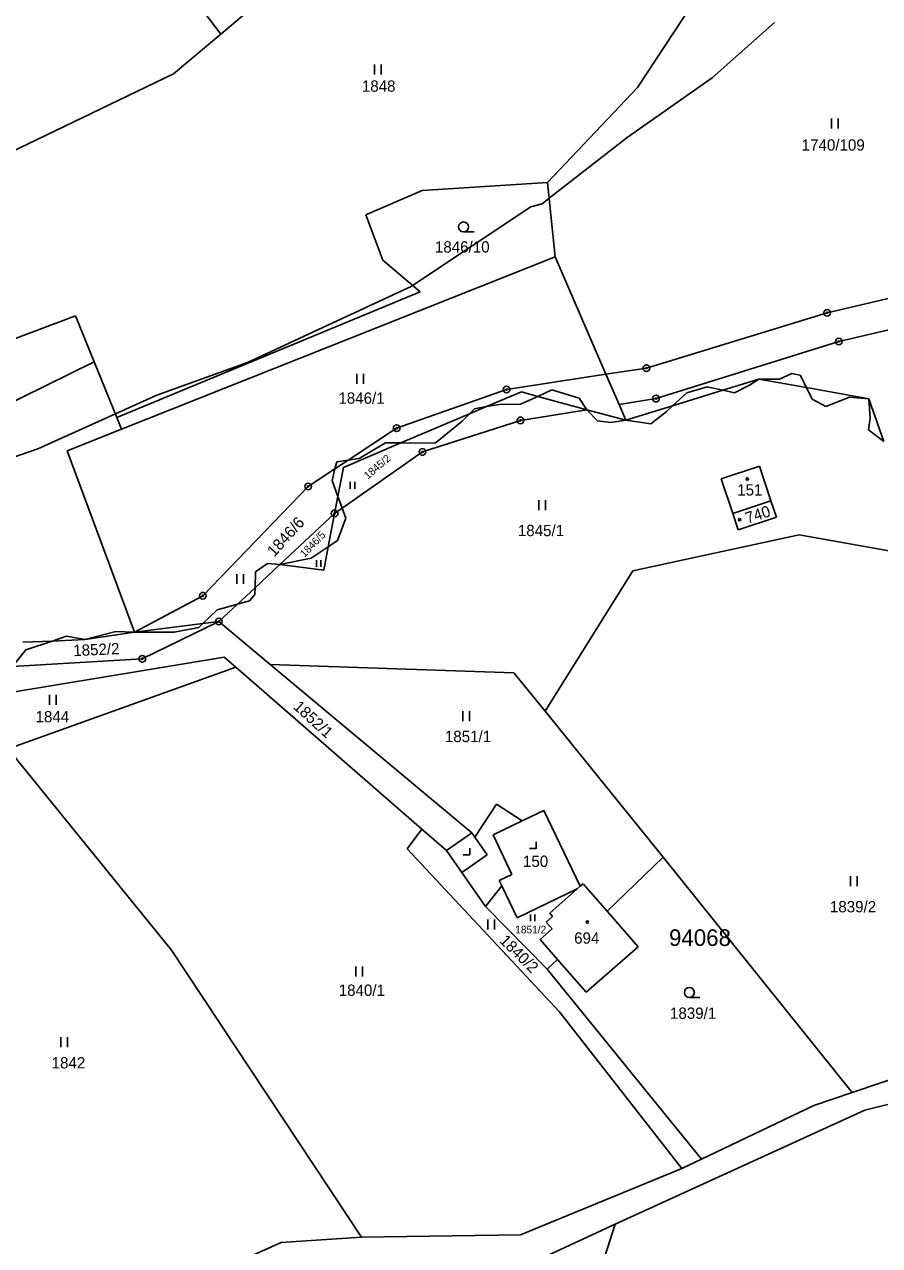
# Model space of a CAD drawing. Extents: x -445050 to -440454, y -1134563 to -1129741.
# Drawn here: x -443566 to -443437.5, y -1133613.8 to -1133430.3 of the extents above; entities that cross this region are included whole.
import ezdxf

# ---------------------------------------------------------------- set-up
doc = ezdxf.new("R2010")
doc.units = 0
for name, color, linetype in [('Vrstva 1', 7, 'Continuous'), ('Vrstva 16', 7, 'Continuous'), ('Vrstva 18', 7, 'Continuous'), ('Vrstva 19', 7, 'Continuous'), ('Vrstva 24', 7, 'Continuous'), ('Vrstva 25', 7, 'Continuous'), ('Vrstva 3', 7, 'Continuous'), ('Vrstva 37', 7, 'Continuous'), ('Vrstva 4', 7, 'Continuous'), ('Vrstva 52', 7, 'Continuous'), ('Vrstva 53', 7, 'Continuous'), ('Vrstva 6', 7, 'Continuous')]:
    doc.layers.add(name, color=color, linetype=linetype)

msp = doc.modelspace()

# ---------------------------------------------------------------- linework, layer by layer
at = {"layer": 'Vrstva 1'}
for p, q in [((-443551.44, -1133491.11), (-443486.28, -1133465.21)), ((-443599.13, -1133502.43), (-443555.56, -1133480.99)), ((-443551.44, -1133491.11), (-443552.14, -1133489.36)), ((-443559.63, -1133494.37), (-443551.44, -1133491.11)), ((-443453.87, -1133501.88), (-443453.05, -1133504.34)), ((-443458.81, -1133506.24), (-443459.62, -1133503.79)), ((-443453.05, -1133504.34), (-443458.81, -1133506.24)), ((-443482.53, -1133559.8), (-443487.99, -1133548.43)), ((-443470.05, -1133555.41), (-443478.47, -1133563.55)), ((-443482.99, -1133560.2), (-443482.53, -1133559.8)), ((-443482.53, -1133559.8), (-443482.09, -1133559.41)), ((-443482.09, -1133559.41), (-443478.47, -1133563.55)), ((-443482.99, -1133560.2), (-443492.02, -1133564.54)), ((-443487.1, -1133563.84), (-443482.99, -1133560.2)), ((-443478.47, -1133563.55), (-443473.82, -1133568.88)), ((-443487.64, -1133565.19), (-443486.67, -1133564.33)), ((-443486.74, -1133566.21), (-443487.64, -1133565.19)), ((-443486.67, -1133564.33), (-443487.1, -1133563.84)), ((-443488.57, -1133567.82), (-443486.74, -1133566.21)), ((-443485.96, -1133570.79), (-443488.57, -1133567.82)), ((-443473.82, -1133568.88), (-443481.62, -1133575.73)), ((-443485.96, -1133570.79), (-443487.47, -1133572.25)), ((-443481.62, -1133575.73), (-443485.96, -1133570.79))]:
    msp.add_line(p, q, dxfattribs=at)
for points in [[(-443506.28, -1133455.25), (-443514.75, -1133458.87)], [(-443506.28, -1133455.25), (-443487.43, -1133454.01)], [(-443486.28, -1133465.21), (-443487.43, -1133454.01)], [(-443512.2, -1133465.69), (-443514.75, -1133458.87)], [(-443445.42, -1133473.61), (-443396.96, -1133462.27)], [(-443512.2, -1133465.69), (-443506.58, -1133470.48)], [(-443478.66, -1133482.85), (-443486.28, -1133465.21)], [(-443393.63, -1133466.27), (-443443.68, -1133477.93)], [(-443506.58, -1133470.48), (-443552.14, -1133489.36)], [(-443472.59, -1133481.92), (-443445.42, -1133473.61)], [(-443579.17, -1133481.9), (-443558.39, -1133474.08)], [(-443558.39, -1133474.08), (-443555.56, -1133480.99)], [(-443443.68, -1133477.93), (-443471.14, -1133486.51)], [(-443555.56, -1133480.99), (-443552.14, -1133489.36)], [(-443493.59, -1133485.15), (-443478.66, -1133482.85)], [(-443478.66, -1133482.85), (-443472.59, -1133481.92)], [(-443476.69, -1133487.4), (-443478.66, -1133482.85)], [(-443461.09, -1133485.25), (-443455.7, -1133483.58)], [(-443455.7, -1133483.58), (-443448.55, -1133484.85)], [(-443510.11, -1133490.96), (-443493.59, -1133485.15)], [(-443496.62, -1133487.72), (-443491.36, -1133485.49)], [(-443491.36, -1133485.49), (-443488.89, -1133486.17)], [(-443488.89, -1133486.17), (-443481.52, -1133488.18)], [(-443471.14, -1133486.51), (-443476.69, -1133487.4)], [(-443468.64, -1133487.59), (-443461.09, -1133485.25)], [(-443448.55, -1133484.85), (-443439.14, -1133486.52)], [(-443439.14, -1133486.52), (-443436.92, -1133492.94)], [(-443499.18, -1133488.81), (-443496.62, -1133487.72)], [(-443481.52, -1133488.18), (-443491.51, -1133489.78)], [(-443481.52, -1133488.18), (-443475.67, -1133489.77)], [(-443476.69, -1133487.4), (-443475.67, -1133489.77)], [(-443475.67, -1133489.77), (-443468.64, -1133487.59)], [(-443509.48, -1133493.18), (-443499.18, -1133488.81)], [(-443491.51, -1133489.78), (-443506.22, -1133494.53)], [(-443517.4, -1133495.75), (-443510.11, -1133490.96)], [(-443518.11, -1133496.84), (-443509.48, -1133493.18)], [(-443559.63, -1133494.37), (-443549.51, -1133521.63)], [(-443519.38, -1133497.05), (-443517.4, -1133495.75)], [(-443506.22, -1133494.53), (-443518.3, -1133502.97)], [(-443523.42, -1133499.71), (-443519.38, -1133497.05)], [(-443518.11, -1133496.84), (-443518.94, -1133501.21)], [(-443461.33, -1133498.56), (-443455.59, -1133496.66)], [(-443455.59, -1133496.66), (-443453.87, -1133501.88)], [(-443459.62, -1133503.79), (-443461.33, -1133498.56)], [(-443539.23, -1133516.13), (-443523.42, -1133499.71)], [(-443518.94, -1133501.21), (-443519.43, -1133503.76)], [(-443518.3, -1133502.97), (-443519.43, -1133503.76)], [(-443453.87, -1133501.88), (-443459.62, -1133503.79)], [(-443519.43, -1133503.76), (-443527.66, -1133511.46)], [(-443519.43, -1133503.76), (-443520.39, -1133508.77)], [(-443449.65, -1133506.99), (-443474.61, -1133512.38)], [(-443421.76, -1133511.95), (-443449.65, -1133506.99)], [(-443520.39, -1133508.77), (-443521.06, -1133512.3)], [(-443527.66, -1133511.46), (-443531.38, -1133514.94)], [(-443527.66, -1133511.46), (-443521.06, -1133512.3)], [(-443474.61, -1133512.38), (-443487.82, -1133533.5)], [(-443531.38, -1133514.94), (-443534.02, -1133517.4)], [(-443549.51, -1133521.63), (-443539.23, -1133516.13)], [(-443534.02, -1133517.4), (-443536.82, -1133520.02)], [(-443549.51, -1133521.63), (-443539.23, -1133520.33)], [(-443536.82, -1133520.02), (-443548.33, -1133525.61)], [(-443539.23, -1133520.33), (-443536.82, -1133520.02)], [(-443536.82, -1133520.02), (-443529.11, -1133526.46)], [(-443566.28, -1133523.13), (-443561.9, -1133522.94)], [(-443561.9, -1133522.94), (-443556.95, -1133522.73)], [(-443556.95, -1133522.73), (-443549.51, -1133521.63)], [(-443573.35, -1133531.52), (-443536.03, -1133525.36)], [(-443568.51, -1133539.16), (-443534.27, -1133526.89)], [(-443548.33, -1133525.61), (-443567.83, -1133526.76)], [(-443534.27, -1133526.89), (-443536.03, -1133525.36)], [(-443506.32, -1133551.22), (-443534.27, -1133526.89)], [(-443529.11, -1133526.46), (-443492.49, -1133527.73)], [(-443498.8, -1133551.77), (-443529.11, -1133526.46)], [(-443492.49, -1133527.73), (-443487.82, -1133533.5)], [(-443487.82, -1133533.5), (-443470.05, -1133555.41)], [(-443568.51, -1133539.16), (-443543.96, -1133569.4)], [(-443498.34, -1133552.43), (-443495.12, -1133547.46)], [(-443495.12, -1133547.46), (-443491.23, -1133549.98)], [(-443487.99, -1133548.43), (-443491.23, -1133549.98)], [(-443506.32, -1133551.22), (-443508.51, -1133554.18)], [(-443502.62, -1133554.44), (-443506.32, -1133551.22)], [(-443498.8, -1133551.77), (-443502.62, -1133554.44)], [(-443498.34, -1133552.43), (-443498.8, -1133551.77)], [(-443508.51, -1133554.18), (-443485.69, -1133578.6)], [(-443502.62, -1133554.44), (-443500.31, -1133557.75)], [(-443470.05, -1133555.41), (-443441.64, -1133590.79)], [(-443500.31, -1133557.75), (-443496.75, -1133562.85)], [(-443496.75, -1133562.85), (-443494.31, -1133559.75)], [(-443492.02, -1133564.54), (-443494.31, -1133559.75)], [(-443496.75, -1133562.85), (-443487.47, -1133572.25)], [(-443543.96, -1133569.4), (-443515.38, -1133612.54)], [(-443487.47, -1133572.25), (-443464.28, -1133600.79)], [(-443485.69, -1133578.6), (-443467.26, -1133602.21)], [(-443441.64, -1133590.79), (-443424.87, -1133585.13)], [(-443447.41, -1133592.74), (-443441.64, -1133590.79)], [(-443439.76, -1133593.44), (-443427.25, -1133590.33)], [(-443464.28, -1133600.79), (-443447.41, -1133592.74)], [(-443477.3, -1133610.57), (-443439.76, -1133593.44)], [(-443467.26, -1133602.21), (-443464.28, -1133600.79)], [(-443491.51, -1133612.18), (-443467.26, -1133602.21)], [(-443477.3, -1133610.57), (-443509.39, -1133710.88)], [(-443488.94, -1133616), (-443477.3, -1133610.57)], [(-443527.48, -1133613.35), (-443515.38, -1133612.54)], [(-443515.38, -1133612.54), (-443491.51, -1133612.18)], [(-443559.66, -1133627.77), (-443527.48, -1133613.35)]]:
    msp.add_lwpolyline(points, dxfattribs=at)
at = {"layer": 'Vrstva 24'}
for centre, radius in [((-443445.42, -1133473.61), 0.5), ((-443445.42, -1133473.61), 0.1), ((-443443.68, -1133477.93), 0.5), ((-443443.68, -1133477.93), 0.1), ((-443472.59, -1133481.92), 0.5), ((-443472.59, -1133481.92), 0.1), ((-443493.59, -1133485.15), 0.5), ((-443493.59, -1133485.15), 0.1), ((-443471.14, -1133486.51), 0.5), ((-443471.14, -1133486.51), 0.1), ((-443491.51, -1133489.78), 0.5), ((-443491.51, -1133489.78), 0.1), ((-443510.11, -1133490.96), 0.5), ((-443510.11, -1133490.96), 0.1), ((-443506.22, -1133494.53), 0.5), ((-443506.22, -1133494.53), 0.1), ((-443523.42, -1133499.71), 0.5), ((-443523.42, -1133499.71), 0.1), ((-443519.43, -1133503.76), 0.5), ((-443519.43, -1133503.76), 0.1), ((-443539.23, -1133516.13), 0.5), ((-443539.23, -1133516.13), 0.1), ((-443536.82, -1133520.02), 0.5), ((-443536.82, -1133520.02), 0.1), ((-443548.33, -1133525.61), 0.5), ((-443548.33, -1133525.61), 0.1)]:
    msp.add_circle(centre, radius, dxfattribs=at)
at = {"layer": 'Vrstva 25'}
for p, q in [((-443513.42, -1133437.78), (-443513.42, -1133436.28)), ((-443512.42, -1133437.78), (-443512.42, -1133436.28)), ((-443444.77, -1133445.91), (-443444.77, -1133444.41)), ((-443443.77, -1133445.91), (-443443.77, -1133444.41)), ((-443500.06, -1133461.46), (-443498.46, -1133461.46)), ((-443516.11, -1133484.3), (-443516.11, -1133482.8)), ((-443515.11, -1133484.3), (-443515.11, -1133482.8)), ((-443517.09, -1133500.05), (-443517.09, -1133499.04)), ((-443516.42, -1133500.05), (-443516.42, -1133499.04)), ((-443488.74, -1133503.29), (-443488.74, -1133501.79)), ((-443487.74, -1133503.29), (-443487.74, -1133501.79)), ((-443522.16, -1133511.78), (-443522.16, -1133510.78)), ((-443521.48, -1133511.78), (-443521.48, -1133510.78)), ((-443534.15, -1133514.37), (-443534.15, -1133512.87)), ((-443533.15, -1133514.37), (-443533.15, -1133512.87)), ((-443562.27, -1133532.52), (-443562.27, -1133531.02)), ((-443561.27, -1133532.52), (-443561.27, -1133531.02)), ((-443500.15, -1133534.97), (-443500.15, -1133533.47)), ((-443499.15, -1133534.97), (-443499.15, -1133533.47)), ((-443441.92, -1133559.8), (-443441.92, -1133558.3)), ((-443440.92, -1133559.8), (-443440.92, -1133558.3)), ((-443496.39, -1133566.31), (-443496.39, -1133564.81)), ((-443495.39, -1133566.31), (-443495.39, -1133564.81)), ((-443490.02, -1133565.02), (-443490.02, -1133564.02)), ((-443489.35, -1133565.02), (-443489.35, -1133564.02)), ((-443516.23, -1133573.35), (-443516.23, -1133571.85)), ((-443515.23, -1133573.35), (-443515.23, -1133571.85)), ((-443466.13, -1133576.51), (-443464.53, -1133576.51)), ((-443560.59, -1133583.99), (-443560.59, -1133582.49)), ((-443559.59, -1133583.99), (-443559.59, -1133582.49))]:
    msp.add_line(p, q, dxfattribs=at)
for points in [[(-443500.13, -1133555.06), (-443499.13, -1133555.06), (-443499.13, -1133554.06)], [(-443490.14, -1133554.11), (-443489.14, -1133554.11), (-443489.14, -1133553.11)]]:
    msp.add_lwpolyline(points, dxfattribs=at)
for centre, radius in [((-443500.06, -1133460.71), 0.75), ((-443457.43, -1133498.57), 0.175), ((-443458.57, -1133504.69), 0.175), ((-443481.44, -1133565.19), 0.175), ((-443466.13, -1133575.76), 0.75)]:
    msp.add_circle(centre, radius, dxfattribs=at)
at = {"layer": 'Vrstva 3'}
for points in [[(-443461.33, -1133498.56), (-443455.59, -1133496.66)], [(-443455.59, -1133496.66), (-443453.87, -1133501.88)], [(-443459.62, -1133503.79), (-443461.33, -1133498.56)], [(-443453.87, -1133501.88), (-443453.05, -1133504.34)], [(-443458.81, -1133506.24), (-443459.62, -1133503.79)], [(-443453.05, -1133504.34), (-443458.81, -1133506.24)], [(-443482.99, -1133560.2), (-443482.53, -1133559.8)], [(-443482.53, -1133559.8), (-443482.09, -1133559.41)], [(-443482.09, -1133559.41), (-443478.47, -1133563.55)], [(-443487.1, -1133563.84), (-443482.99, -1133560.2)], [(-443478.47, -1133563.55), (-443473.82, -1133568.88)], [(-443487.64, -1133565.19), (-443486.67, -1133564.33)], [(-443486.74, -1133566.21), (-443487.64, -1133565.19)], [(-443486.67, -1133564.33), (-443487.1, -1133563.84)], [(-443488.57, -1133567.82), (-443486.74, -1133566.21)], [(-443485.96, -1133570.79), (-443488.57, -1133567.82)], [(-443473.82, -1133568.88), (-443481.62, -1133575.73)], [(-443481.62, -1133575.73), (-443485.96, -1133570.79)]]:
    msp.add_lwpolyline(points, dxfattribs=at)
at = {"layer": 'Vrstva 37'}
for centre in [(-443457.43, -1133498.57), (-443481.44, -1133565.19)]:
    msp.add_circle(centre, 0.175, dxfattribs=at)
at = {"layer": 'Vrstva 4'}
for points in [[(-443452.56, -1133483.57), (-443450.73, -1133482.74)], [(-443450.73, -1133482.74), (-443449.5, -1133482.98)], [(-443466.52, -1133485.63), (-443463.45, -1133484.74)], [(-443463.45, -1133484.74), (-443461.09, -1133485.25)], [(-443459.33, -1133485.63), (-443457.09, -1133484.51)], [(-443457.09, -1133484.51), (-443455.7, -1133483.58)], [(-443455.7, -1133483.58), (-443452.56, -1133483.57)], [(-443449.5, -1133482.98), (-443448.55, -1133484.85)], [(-443491.48, -1133487.34), (-443488.89, -1133486.17)], [(-443488.89, -1133486.17), (-443486.77, -1133485.21)], [(-443486.77, -1133485.21), (-443482.7, -1133486.45)], [(-443482.7, -1133486.45), (-443481.52, -1133488.18)], [(-443468.64, -1133487.59), (-443466.52, -1133485.63)], [(-443461.09, -1133485.25), (-443459.33, -1133485.63)], [(-443448.55, -1133484.85), (-443447.67, -1133486.57)], [(-443447.67, -1133486.57), (-443445.61, -1133487.69)], [(-443445.61, -1133487.69), (-443442.08, -1133486.28)], [(-443442.08, -1133486.28), (-443439.14, -1133486.52)], [(-443439.14, -1133486.52), (-443438.96, -1133489.46)], [(-443499.18, -1133488.81), (-443498.43, -1133488.04)], [(-443498.43, -1133488.04), (-443496.62, -1133487.72)], [(-443496.62, -1133487.72), (-443494.72, -1133487.39)], [(-443494.72, -1133487.39), (-443491.48, -1133487.34)], [(-443481.52, -1133488.18), (-443479.94, -1133489.87)], [(-443469.63, -1133488.51), (-443468.64, -1133487.59)], [(-443504.33, -1133493.22), (-443500.27, -1133489.92)], [(-443500.27, -1133489.92), (-443499.18, -1133488.81)], [(-443479.94, -1133489.87), (-443477.93, -1133490.1)], [(-443477.93, -1133490.1), (-443475.67, -1133489.77)], [(-443475.67, -1133489.77), (-443471.93, -1133490.28)], [(-443471.93, -1133490.28), (-443469.63, -1133488.51)], [(-443438.96, -1133489.46), (-443439.19, -1133491.22)], [(-443439.19, -1133491.22), (-443436.92, -1133492.94)], [(-443515.75, -1133495.52), (-443511.81, -1133493.16)], [(-443511.81, -1133493.16), (-443509.48, -1133493.18)], [(-443509.48, -1133493.18), (-443504.33, -1133493.22)], [(-443519.11, -1133495.99), (-443517.4, -1133495.75)], [(-443517.4, -1133495.75), (-443515.75, -1133495.52)], [(-443519.82, -1133498.82), (-443519.38, -1133497.05)], [(-443519.38, -1133497.05), (-443519.11, -1133495.99)], [(-443518.94, -1133501.21), (-443519.82, -1133498.82)], [(-443518.3, -1133502.97), (-443518.94, -1133501.21)], [(-443517.75, -1133504.47), (-443518.3, -1133502.97)], [(-443518.99, -1133507.83), (-443517.75, -1133504.47)], [(-443520.39, -1133508.77), (-443518.99, -1133507.83)], [(-443522.94, -1133510.48), (-443520.39, -1133508.77)], [(-443531.3, -1133512.54), (-443529.53, -1133511.31)], [(-443529.53, -1133511.31), (-443527.66, -1133511.46)], [(-443527.66, -1133511.46), (-443522.94, -1133510.48)], [(-443531.38, -1133514.94), (-443531.3, -1133512.54)], [(-443531.42, -1133515.96), (-443531.38, -1133514.94)], [(-443537.07, -1133518.26), (-443534.02, -1133517.4)], [(-443534.02, -1133517.4), (-443532.24, -1133516.9)], [(-443532.24, -1133516.9), (-443531.42, -1133515.96)], [(-443539.23, -1133520.33), (-443537.07, -1133518.26)], [(-443543.55, -1133521.62), (-443539.84, -1133520.91)], [(-443539.84, -1133520.91), (-443539.23, -1133520.33)], [(-443565.81, -1133524.27), (-443561.9, -1133522.94)], [(-443561.9, -1133522.94), (-443559.74, -1133522.21)], [(-443559.74, -1133522.21), (-443556.95, -1133522.73)], [(-443556.95, -1133522.73), (-443552.32, -1133521.5)], [(-443552.32, -1133521.5), (-443549.51, -1133521.63)], [(-443549.51, -1133521.63), (-443543.55, -1133521.62)], [(-443567.83, -1133526.76), (-443565.81, -1133524.27)], [(-443491.23, -1133549.98), (-443495.63, -1133552.09)], [(-443498.34, -1133552.43), (-443496.49, -1133555.08)], [(-443492.79, -1133558.01), (-443495.63, -1133552.09)], [(-443500.31, -1133557.75), (-443496.49, -1133555.08)], [(-443492.79, -1133558.01), (-443494.7, -1133558.93)], [(-443494.31, -1133559.75), (-443494.7, -1133558.93)]]:
    msp.add_lwpolyline(points, dxfattribs=at)
at = {"layer": 'Vrstva 52'}
msp.add_lwpolyline([(-443651.73, -1133534.31), (-443651.56, -1133534.26), (-443638.96, -1133530.9), (-443631.3, -1133526.86), (-443627.13, -1133524.12), (-443622.08, -1133520.81), (-443621.45, -1133520.4), (-443617.67, -1133517.92), (-443608.49, -1133513.07), (-443602.35, -1133509.83), (-443587.02, -1133503.44), (-443577.65, -1133498.76), (-443564.03, -1133494.08), (-443552.37, -1133488.8), (-443546.15, -1133485.99), (-443532.53, -1133481.09), (-443507.84, -1133469.6), (-443507.71, -1133469.52), (-443489.95, -1133457.68), (-443488.25, -1133457.25), (-443487.18, -1133456.41), (-443475.48, -1133447.25), (-443462.71, -1133438.31), (-443453.34, -1133430)], dxfattribs=at)
at = {"layer": 'Vrstva 6'}
for points in [[(-443572.86, -1133384.07), (-443536.53, -1133431.72)], [(-443521.99, -1133419.43), (-443536.53, -1133431.72)], [(-443473.92, -1133439.73), (-443465.7, -1133427.26)], [(-443536.53, -1133431.72), (-443543.62, -1133437.72)], [(-443543.62, -1133437.72), (-443583.42, -1133456.82)], [(-443487.43, -1133454.01), (-443473.92, -1133439.73)]]:
    msp.add_lwpolyline(points, dxfattribs=at)

# ---------------------------------------------------------------- texts
at = {"layer": 'Vrstva 16'}
msp.add_text('1839/2', height=1.7, dxfattribs=at).set_placement((-443445.01, -1133563.72))
at = {"layer": 'Vrstva 18'}
for s, height, p in [('1848', 1.7, (-443515.34, -1133440.39)), ('1740/109', 1.7, (-443449.25, -1133449.24)), ('1846/10', 1.7, (-443504.36, -1133464.56)), ('1846/1', 1.7, (-443518.87, -1133487.28)), ('1845/1', 1.7, (-443491.9, -1133507.18)), ('1844', 1.7, (-443564.38, -1133535.16)), ('1851/1', 1.7, (-443502.87, -1133538.13)), ('1851/2', 1.14, (-443492.3, -1133566.87)), ('1840/1', 1.7, (-443518.82, -1133576.27)), ('1839/1', 1.7, (-443469.04, -1133579.72)), ('1842', 1.7, (-443561.96, -1133587.18))]:
    msp.add_text(s, height=height, dxfattribs=at).set_placement(p)
for s, height, rotation, p in [('1845/2', 1.14, 40.8151, (-443514.43, -1133498.7)), ('1846/6', 1.7, 47.9043, (-443528.5, -1133510.4)), ('1846/5', 1.14, 46.0051, (-443523.95, -1133510.45)), ('1852/2', 1.7, 2.6496, (-443558.67, -1133525.23)), ('1852/1', 1.7, 317.5839, (-443525.77, -1133532.98)), ('1840/2', 1.7, 315.4941, (-443494.78, -1133568.1))]:
    msp.add_text(s, height=height, rotation=rotation, dxfattribs=at).set_placement(p)
at = {"layer": 'Vrstva 19'}
for s, p in [('151', (-443458.94, -1133501.08)), ('150', (-443491.13, -1133556.89)), ('694', (-443483.44, -1133568.43))]:
    msp.add_text(s, height=1.7, dxfattribs=at).set_placement(p)
msp.add_text('740', height=1.7, rotation=18.2557, dxfattribs=at).set_placement((-443457.38, -1133505.32))
at = {"layer": 'Vrstva 53'}
msp.add_text('94068', height=2.5, dxfattribs=at).set_placement((-443469.18, -1133568.77))

doc.saveas('drawing.dxf')
